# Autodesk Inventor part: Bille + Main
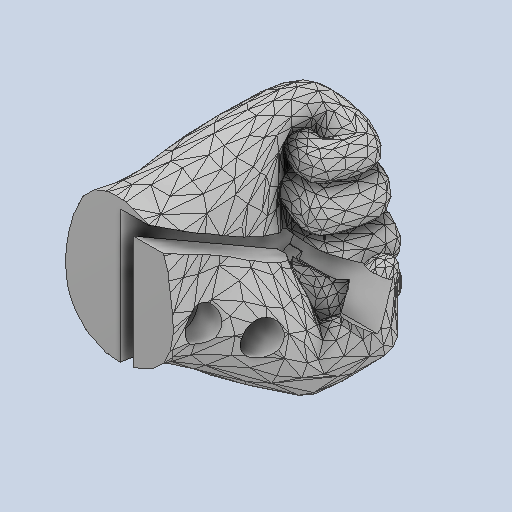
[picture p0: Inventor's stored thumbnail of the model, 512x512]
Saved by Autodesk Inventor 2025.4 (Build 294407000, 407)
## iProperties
Created: 2026-06
Part Number: Bille + Main
Material: Generic
Document SubType Name: Modeling
Designer: AdminForWorker
Density: 1 g/cm^3
Appearance: Default
Title: Bille + Main v7
Author: AdminForWorker
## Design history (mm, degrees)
feature "fist"
body "Solid1"
